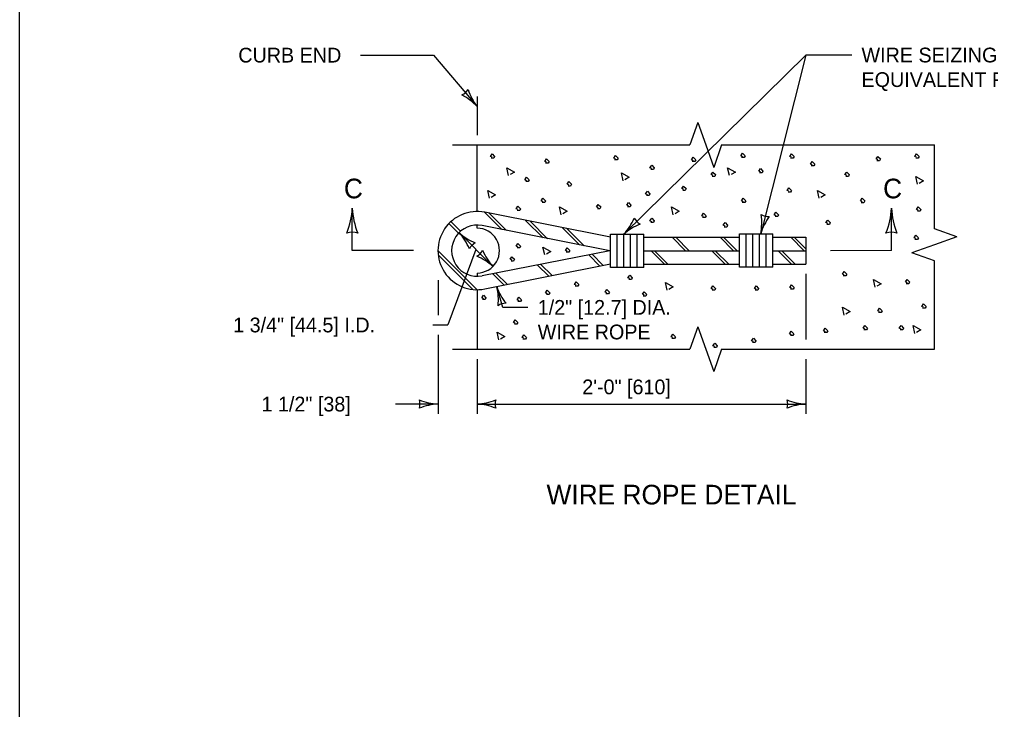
# Model space of a CAD drawing. Extents: x 49991.4 to 50021, y 49987.6 to 50011.4.
# Drawn here: x 49999.384 to 50003.334, y 49991.042 to 49993.85 of the extents above; entities that cross this region are included whole.
import ezdxf

# ---------------------------------------------------------------- set-up
doc = ezdxf.new("R2010")
doc.units = 0
for name, color, linetype in [('Level 1', 7, 'Continuous'), ('Level 2', 7, 'Continuous'), ('Level 3', 7, 'Continuous'), ('Level 6', 7, 'Continuous')]:
    doc.layers.add(name, color=color, linetype=linetype)

msp = doc.modelspace()

# ---------------------------------------------------------------- linework, layer by layer
at = {"layer": 'Level 1'}
for p, q in [((50001.245, 49993.0684), (50001.245, 49993.3392)), ((50001.2758, 49993.0654), (50001.3461, 49992.9952)), ((50001.7873, 49992.9636), (50001.276, 49993.0653)), ((50001.2937, 49993.0618), (50001.3647, 49992.9912)), ((50001.1303, 49993.0196), (50001.1694, 49992.9806)), ((50001.1385, 49993.0275), (50001.178, 49992.9885)), ((50001.245, 49993.0009), (50001.245, 49993.013)), ((50001.7854, 49992.9084), (50001.2652, 49993.011)), ((50001.4426, 49993.0322), (50001.5134, 49992.9615)), ((50001.4607, 49993.0286), (50001.5314, 49992.9575)), ((50001.5924, 49993.0024), (50001.6621, 49992.9324)), ((50001.61, 49992.9989), (50001.6806, 49992.9283)), ((50001.7873, 49992.976), (50001.923, 49992.976)), ((50001.7873, 49992.8403), (50001.7873, 49992.976)), ((50001.7873, 49992.9636), (50001.7873, 49992.9636)), ((50001.8145, 49992.8403), (50001.8145, 49992.976)), ((50001.8415, 49992.8403), (50001.8415, 49992.976)), ((50001.8688, 49992.8403), (50001.8688, 49992.976)), ((50001.8958, 49992.8403), (50001.8958, 49992.976)), ((50001.923, 49992.8403), (50001.923, 49992.976)), ((50001.923, 49992.9636), (50002.3128, 49992.9636)), ((50002.0391, 49992.9636), (50002.0932, 49992.9091)), ((50002.0531, 49992.9636), (50002.1072, 49992.9091)), ((50002.2337, 49992.9641), (50002.2884, 49992.9091)), ((50002.248, 49992.9641), (50002.3025, 49992.9091)), ((50002.3128, 49992.978), (50002.4483, 49992.978)), ((50002.3128, 49992.8424), (50002.3128, 49992.978)), ((50002.3399, 49992.8424), (50002.3399, 49992.978)), ((50002.3668, 49992.8424), (50002.3668, 49992.978)), ((50002.3943, 49992.8424), (50002.3943, 49992.978)), ((50002.4209, 49992.8424), (50002.4209, 49992.978)), ((50002.4483, 49992.8424), (50002.4483, 49992.978)), ((50002.4483, 49992.9636), (50002.582, 49992.9636)), ((50002.5214, 49992.9636), (50002.5761, 49992.9091)), ((50002.5351, 49992.9636), (50002.582, 49992.9169)), ((50002.582, 49992.9636), (50002.582, 49992.8548)), ((50001.086, 49992.9096), (50001.245, 49992.7503)), ((50001.0869, 49992.8922), (50001.2276, 49992.7513)), ((50001.7854, 49992.9084), (50001.2651, 49992.8073)), ((50001.6998, 49992.8918), (50001.7449, 49992.8465)), ((50001.7134, 49992.8945), (50001.7584, 49992.8492)), ((50001.923, 49992.9091), (50002.3128, 49992.9091)), ((50001.9532, 49992.9091), (50002.0075, 49992.8549)), ((50001.9672, 49992.9091), (50002.0211, 49992.8549)), ((50002.2001, 49992.9091), (50002.2546, 49992.8549)), ((50002.214, 49992.9091), (50002.2686, 49992.8549)), ((50002.4483, 49992.9091), (50002.582, 49992.9091)), ((50002.4699, 49992.9091), (50002.5242, 49992.8548)), ((50002.484, 49992.9091), (50002.5382, 49992.8548)), ((50001.7873, 49992.8549), (50001.2761, 49992.7531)), ((50001.4912, 49992.8502), (50001.5363, 49992.805)), ((50001.5034, 49992.8539), (50001.5498, 49992.8077)), ((50001.7873, 49992.8549), (50001.7873, 49992.8549)), ((50001.923, 49992.8549), (50002.3128, 49992.8549)), ((50002.4483, 49992.8548), (50002.582, 49992.8548)), ((50001.245, 49992.8178), (50001.245, 49992.8054)), ((50001.3081, 49992.8157), (50001.355, 49992.7689)), ((50001.3215, 49992.8183), (50001.3682, 49992.7715)), ((50001.923, 49992.8403), (50001.7873, 49992.8403)), ((50002.4483, 49992.8424), (50002.3128, 49992.8424)), ((50001.245, 49992.7503), (50001.245, 49992.5083))]:
    msp.add_line(p, q, dxfattribs=at)
msp.add_lwpolyline([(49999.3835, 49998.9992), (50016.7501, 49998.9992), (50016.7501, 49987.7988), (49999.3835, 49987.7988)], close=True, dxfattribs=at)
for points in [[(50001.306, 49993.2894), (50001.299, 49993.293), (50001.306, 49993.3036), (50001.3165, 49993.293), (50001.313, 49993.2859), (50001.3025, 49993.2859)], [(50001.5271, 49993.2681), (50001.5201, 49993.2717), (50001.5271, 49993.2823), (50001.5376, 49993.2717), (50001.5341, 49993.2646), (50001.5236, 49993.2646)], [(50001.8079, 49993.2823), (50001.8009, 49993.2859), (50001.8079, 49993.2965), (50001.8184, 49993.2859), (50001.8149, 49993.2788), (50001.8044, 49993.2788)], [(50002.1237, 49993.2752), (50002.1167, 49993.2788), (50002.1237, 49993.2894), (50002.1342, 49993.2788), (50002.1307, 49993.2717), (50002.1202, 49993.2717)], [(50002.3246, 49993.2913), (50002.3176, 49993.2949), (50002.3246, 49993.3055), (50002.3351, 49993.2949), (50002.3316, 49993.2878), (50002.3211, 49993.2878)], [(50002.5238, 49993.2894), (50002.5168, 49993.293), (50002.5238, 49993.3036), (50002.5343, 49993.293), (50002.5308, 49993.2859), (50002.5203, 49993.2859)], [(50002.8748, 49993.2788), (50002.8678, 49993.2824), (50002.8748, 49993.293), (50002.8853, 49993.2824), (50002.8818, 49993.2753), (50002.8713, 49993.2753)], [(50003.0327, 49993.2894), (50003.0257, 49993.293), (50003.0327, 49993.3036), (50003.0432, 49993.293), (50003.0397, 49993.2859), (50003.0292, 49993.2859)], [(50001.3728, 49993.2149), (50001.3657, 49993.2469), (50001.3973, 49993.2291), (50001.3798, 49993.2185)], [(50001.9553, 49993.2433), (50001.9483, 49993.2469), (50001.9553, 49993.2575), (50001.9658, 49993.2469), (50001.9623, 49993.2398), (50001.9518, 49993.2398)], [(50002.2712, 49993.2149), (50002.2641, 49993.2469), (50002.2957, 49993.2291), (50002.2782, 49993.2185)], [(50002.3975, 49993.2291), (50002.3905, 49993.2327), (50002.3975, 49993.2433), (50002.408, 49993.2327), (50002.4045, 49993.2256), (50002.394, 49993.2256)], [(50002.6081, 49993.2575), (50002.6011, 49993.2611), (50002.6081, 49993.2717), (50002.6186, 49993.2611), (50002.6151, 49993.254), (50002.6046, 49993.254)], [(50001.4464, 49993.1936), (50001.4394, 49993.1972), (50001.4464, 49993.2078), (50001.4569, 49993.1972), (50001.4534, 49993.1901), (50001.4429, 49993.1901)], [(50001.8395, 49993.1936), (50001.8324, 49993.2256), (50001.864, 49993.2078), (50001.8465, 49993.1972)], [(50002.2045, 49993.2149), (50002.1975, 49993.2185), (50002.2045, 49993.2291), (50002.215, 49993.2185), (50002.2115, 49993.2114), (50002.201, 49993.2114)], [(50002.7484, 49993.2149), (50002.7414, 49993.2185), (50002.7484, 49993.2291), (50002.7589, 49993.2185), (50002.7554, 49993.2114), (50002.7449, 49993.2114)], [(50003.0363, 49993.1794), (50003.0292, 49993.2114), (50003.0608, 49993.1936), (50003.0433, 49993.183)], [(50001.6184, 49993.1758), (50001.6114, 49993.1794), (50001.6184, 49993.19), (50001.6289, 49993.1794), (50001.6254, 49993.1723), (50001.6149, 49993.1723)], [(50002.0851, 49993.1581), (50002.0781, 49993.1617), (50002.0851, 49993.1723), (50002.0956, 49993.1617), (50002.0921, 49993.1546), (50002.0816, 49993.1546)], [(50002.5133, 49993.151), (50002.5063, 49993.1546), (50002.5133, 49993.1652), (50002.5238, 49993.1546), (50002.5203, 49993.1475), (50002.5098, 49993.1475)], [(50001.2955, 49993.1226), (50001.2884, 49993.1546), (50001.32, 49993.1368), (50001.3025, 49993.1262)], [(50001.5131, 49993.1084), (50001.5061, 49993.112), (50001.5131, 49993.1226), (50001.5236, 49993.112), (50001.5201, 49993.1049), (50001.5096, 49993.1049)], [(50001.9377, 49993.1368), (50001.9307, 49993.1404), (50001.9377, 49993.151), (50001.9482, 49993.1404), (50001.9447, 49993.1333), (50001.9342, 49993.1333)], [(50002.3273, 49993.1084), (50002.3203, 49993.112), (50002.3273, 49993.1226), (50002.3378, 49993.112), (50002.3343, 49993.1049), (50002.3238, 49993.1049)], [(50002.6362, 49993.1226), (50002.6291, 49993.1546), (50002.6607, 49993.1368), (50002.6432, 49993.1262)], [(50002.8115, 49993.108), (50002.8045, 49993.1116), (50002.8115, 49993.1222), (50002.822, 49993.1116), (50002.8185, 49993.1045), (50002.808, 49993.1045)], [(50001.4113, 49993.0764), (50001.4043, 49993.08), (50001.4113, 49993.0906), (50001.4218, 49993.08), (50001.4183, 49993.0729), (50001.4078, 49993.0729)], [(50001.5868, 49993.0551), (50001.5797, 49993.0871), (50001.6113, 49993.0693), (50001.5938, 49993.0587)], [(50001.7377, 49993.0835), (50001.7307, 49993.0871), (50001.7377, 49993.0977), (50001.7482, 49993.0871), (50001.7447, 49993.08), (50001.7342, 49993.08)], [(50001.8605, 49993.0906), (50001.8535, 49993.0942), (50001.8605, 49993.1048), (50001.871, 49993.0942), (50001.8675, 49993.0871), (50001.857, 49993.0871)], [(50002.0431, 49993.0551), (50002.036, 49993.0871), (50002.0676, 49993.0693), (50002.0501, 49993.0587)], [(50003.0397, 49993.0729), (50003.0327, 49993.0765), (50003.0397, 49993.0871), (50003.0502, 49993.0765), (50003.0467, 49993.0694), (50003.0362, 49993.0694)], [(50001.9553, 49993.0267), (50001.9483, 49993.0303), (50001.9553, 49993.0409), (50001.9658, 49993.0303), (50001.9623, 49993.0232), (50001.9518, 49993.0232)], [(50002.1659, 49993.048), (50002.1589, 49993.0516), (50002.1659, 49993.0622), (50002.1764, 49993.0516), (50002.1729, 49993.0445), (50002.1624, 49993.0445)], [(50002.4607, 49993.0516), (50002.4537, 49993.0552), (50002.4607, 49993.0658), (50002.4712, 49993.0552), (50002.4677, 49993.0481), (50002.4572, 49993.0481)], [(50002.2536, 49993.009), (50002.2466, 49993.0126), (50002.2536, 49993.0232), (50002.2641, 49993.0126), (50002.2606, 49993.0055), (50002.2501, 49993.0055)], [(50002.6712, 49993.0196), (50002.6642, 49993.0232), (50002.6712, 49993.0338), (50002.6817, 49993.0232), (50002.6782, 49993.0161), (50002.6677, 49993.0161)], [(50003.0296, 49992.9585), (50003.0226, 49992.9621), (50003.0296, 49992.9727), (50003.0401, 49992.9621), (50003.0366, 49992.955), (50003.0261, 49992.955)], [(50001.4113, 49992.9238), (50001.4043, 49992.9274), (50001.4113, 49992.938), (50001.4218, 49992.9274), (50001.4183, 49992.9203), (50001.4078, 49992.9203)], [(50001.5202, 49992.8918), (50001.5131, 49992.9238), (50001.5447, 49992.906), (50001.5272, 49992.8954)], [(50001.3867, 49992.8705), (50001.3797, 49992.8741), (50001.3867, 49992.8847), (50001.3972, 49992.8741), (50001.3937, 49992.867), (50001.3832, 49992.867)], [(50001.6114, 49992.906), (50001.6044, 49992.9096), (50001.6114, 49992.9202), (50001.6219, 49992.9096), (50001.6184, 49992.9025), (50001.6079, 49992.9025)], [(50001.8657, 49992.7953), (50001.8587, 49992.7989), (50001.8657, 49992.8095), (50001.8762, 49992.7989), (50001.8727, 49992.7918), (50001.8622, 49992.7918)], [(50002.7379, 49992.8102), (50002.7309, 49992.8138), (50002.7379, 49992.8244), (50002.7484, 49992.8138), (50002.7449, 49992.8067), (50002.7344, 49992.8067)], [(50001.6481, 49992.7684), (50001.6411, 49992.772), (50001.6481, 49992.7826), (50001.6586, 49992.772), (50001.6551, 49992.7649), (50001.6446, 49992.7649)], [(50002.0185, 49992.7481), (50002.0114, 49992.7801), (50002.043, 49992.7623), (50002.0255, 49992.7517)], [(50002.2045, 49992.7516), (50002.1975, 49992.7552), (50002.2045, 49992.7658), (50002.215, 49992.7552), (50002.2115, 49992.7481), (50002.201, 49992.7481)], [(50002.3799, 49992.7516), (50002.3729, 49992.7552), (50002.3799, 49992.7658), (50002.3904, 49992.7552), (50002.3869, 49992.7481), (50002.3764, 49992.7481)], [(50002.5239, 49992.7554), (50002.5169, 49992.759), (50002.5239, 49992.7696), (50002.5344, 49992.759), (50002.5309, 49992.7519), (50002.5204, 49992.7519)], [(50002.8643, 49992.7605), (50002.8572, 49992.7925), (50002.8888, 49992.7747), (50002.8713, 49992.7641)], [(50002.9941, 49992.7782), (50002.9871, 49992.7818), (50002.9941, 49992.7924), (50003.0046, 49992.7818), (50003.0011, 49992.7747), (50002.9906, 49992.7747)], [(50001.2707, 49992.7137), (50001.2637, 49992.7173), (50001.2707, 49992.7279), (50001.2812, 49992.7173), (50001.2777, 49992.7102), (50001.2672, 49992.7102)], [(50001.5306, 49992.7339), (50001.5236, 49992.7375), (50001.5306, 49992.7481), (50001.5411, 49992.7375), (50001.5376, 49992.7304), (50001.5271, 49992.7304)], [(50001.7728, 49992.7374), (50001.7658, 49992.741), (50001.7728, 49992.7516), (50001.7833, 49992.741), (50001.7798, 49992.7339), (50001.7693, 49992.7339)], [(50001.9243, 49992.728), (50001.9173, 49992.7316), (50001.9243, 49992.7422), (50001.9348, 49992.7316), (50001.9313, 49992.7245), (50001.9208, 49992.7245)], [(50001.4148, 49992.7055), (50001.4078, 49992.7091), (50001.4148, 49992.7197), (50001.4253, 49992.7091), (50001.4218, 49992.702), (50001.4113, 49992.702)], [(50003.0608, 49992.6788), (50003.0538, 49992.6824), (50003.0608, 49992.693), (50003.0713, 49992.6824), (50003.0678, 49992.6753), (50003.0573, 49992.6753)], [(50002.738, 49992.6469), (50002.7309, 49992.6789), (50002.7625, 49992.6611), (50002.745, 49992.6505)], [(50002.8818, 49992.6611), (50002.8748, 49992.6647), (50002.8818, 49992.6753), (50002.8923, 49992.6647), (50002.8888, 49992.6576), (50002.8783, 49992.6576)], [(50001.4001, 49992.6132), (50001.3931, 49992.6168), (50001.4001, 49992.6274), (50001.4106, 49992.6168), (50001.4071, 49992.6097), (50001.3966, 49992.6097)], [(50001.3333, 49992.546), (50001.3262, 49992.578), (50001.3578, 49992.5602), (50001.3403, 49992.5496)], [(50001.4349, 49992.5528), (50001.4279, 49992.5564), (50001.4349, 49992.567), (50001.4454, 49992.5564), (50001.4419, 49992.5493), (50001.4314, 49992.5493)], [(50002.041, 49992.5555), (50002.034, 49992.5591), (50002.041, 49992.5697), (50002.0515, 49992.5591), (50002.048, 49992.552), (50002.0375, 49992.552)], [(50002.5228, 49992.5669), (50002.5158, 49992.5705), (50002.5228, 49992.5811), (50002.5333, 49992.5705), (50002.5298, 49992.5634), (50002.5193, 49992.5634)], [(50002.6607, 49992.5794), (50002.6537, 49992.583), (50002.6607, 49992.5936), (50002.6712, 49992.583), (50002.6677, 49992.5759), (50002.6572, 49992.5759)], [(50002.8221, 49992.59), (50002.8151, 49992.5936), (50002.8221, 49992.6042), (50002.8326, 49992.5936), (50002.8291, 49992.5865), (50002.8186, 49992.5865)], [(50002.9695, 49992.59), (50002.9625, 49992.5936), (50002.9695, 49992.6042), (50002.98, 49992.5936), (50002.9765, 49992.5865), (50002.966, 49992.5865)], [(50003.0258, 49992.5723), (50003.0187, 49992.6043), (50003.0503, 49992.5865), (50003.0328, 49992.5759)], [(50002.2115, 49992.5189), (50002.2045, 49992.5225), (50002.2115, 49992.5331), (50002.222, 49992.5225), (50002.2185, 49992.5154), (50002.208, 49992.5154)], [(50002.3688, 49992.5393), (50002.3618, 49992.5429), (50002.3688, 49992.5535), (50002.3793, 49992.5429), (50002.3758, 49992.5358), (50002.3653, 49992.5358)]]:
    msp.add_lwpolyline(points, dxfattribs=at)
for centre, radius, start, end in [((50001.245, 49992.9094), 0.159, 78.7514, 281.2486), ((50001.2452, 49992.9092), 0.1038, 78.8937, 281.05), ((50001.245, 49992.9094), 0.0912, 269.8974, 90.1017)]:
    msp.add_arc(centre, radius, start, end, dxfattribs=at)
at = {"layer": 'Level 3'}
for p, q in [((50000.7706, 49993.7049), (50001.0675, 49993.7049)), ((50001.0672, 49993.7053), (50001.245, 49993.4961)), ((50002.5818, 49993.7053), (50001.842, 49992.976)), ((50002.5818, 49993.7053), (50002.3987, 49992.978)), ((50002.7687, 49993.7053), (50002.5818, 49993.7053)), ((50001.245, 49993.5361), (50001.245, 49993.3792)), ((50001.3095, 49992.8449), (50001.1717, 49992.9827)), ((50001.2406, 49992.9138), (50001.1262, 49992.6068)), ((50002.582, 49992.8148), (50002.582, 49992.5483)), ((50001.0862, 49992.7892), (50001.0862, 49992.6468)), ((50001.3503, 49992.6783), (50001.3249, 49992.7629)), ((50001.4518, 49992.6783), (50001.3503, 49992.6783)), ((50001.0647, 49992.6068), (50001.1262, 49992.6068)), ((50001.0862, 49992.5668), (50001.0862, 49992.2449)), ((50001.245, 49992.4683), (50001.245, 49992.2449)), ((50002.582, 49992.4683), (50002.582, 49992.2449)), ((50001.0862, 49992.2849), (50000.9127, 49992.2849)), ((50001.245, 49992.2849), (50002.582, 49992.2849))]:
    msp.add_line(p, q, dxfattribs=at)
for centre, radius, start, end in [((50001.162, 49993.5938), 0.0548, 292.4945, 328.2168), ((50001.4202, 49993.6329), 0.2223, 197.8117, 217.9952), ((50001.0751, 49993.3366), 0.233, 43.183, 62.4328), ((50000.4413, 49993.0945), 0.2964, 337.456, 357.6395), ((50001.0477, 49993.0976), 0.3107, 182.8273, 202.0772), ((50002.6343, 49993.0944), 0.2964, 337.456, 357.6395), ((50003.2408, 49993.0975), 0.3107, 182.8273, 202.0772), ((50001.6704, 49993.1337), 0.233, 317.4153, 336.6652), ((50001.9333, 49993.0661), 0.0548, 206.7268, 242.4492), ((50002.1702, 49993.0237), 0.233, 348.6916, 7.9415), ((50002.6118, 49992.9149), 0.2223, 143.3203, 163.5038), ((50002.43, 49993.1024), 0.0548, 238.0031, 273.7255), ((50001.9914, 49992.8114), 0.2223, 112.044, 132.2275), ((50000.7375, 49992.9113), 0.073, 72.1388, 107.8612), ((50001.0082, 49992.8321), 0.2223, 22.456, 42.6395), ((50001.3282, 49993.1554), 0.233, 227.8273, 247.0772), ((50002.9305, 49992.9112), 0.073, 72.1388, 107.8612), ((50001.2624, 49992.892), 0.0548, 117.1388, 152.8612), ((50001.2189, 49992.9356), 0.0548, 297.1388, 332.8612), ((50001.1531, 49992.6722), 0.233, 47.8273, 67.0772), ((50001.4731, 49992.9955), 0.2223, 202.456, 222.6395), ((50001.1095, 49992.7076), 0.2223, 354.2141, 14.3976), ((50001.5444, 49992.841), 0.233, 199.5854, 218.8352), ((50001.3618, 49992.6401), 0.0548, 88.8969, 124.6192), ((50001.0953, 49992.5071), 0.2223, 247.456, 267.6395), ((50000.958, 49992.2849), 0.0548, 342.1388, 17.8612), ((50001.2335, 49992.5177), 0.233, 272.8273, 292.0772), ((50001.3732, 49992.2849), 0.0548, 162.1388, 197.8612), ((50002.5911, 49992.5071), 0.2223, 247.456, 267.6395), ((50002.4538, 49992.2849), 0.0548, 342.1388, 17.8612), ((50001.0977, 49992.0522), 0.233, 92.8273, 112.0772), ((50001.2358, 49992.0628), 0.2223, 67.456, 87.6395), ((50002.5935, 49992.0522), 0.233, 92.8273, 112.0772)]:
    msp.add_arc(centre, radius, start, end, dxfattribs=at)
at = {"layer": 'Level 6'}
for p, q in [((50002.1426, 49993.4306), (50002.1102, 49993.3392)), ((50002.1426, 49993.4306), (50002.175, 49993.3392)), ((50001.145, 49993.3392), (50002.1102, 49993.3392)), ((50002.175, 49993.3392), (50002.2074, 49993.2478)), ((50002.2398, 49993.3392), (50002.2074, 49993.2478)), ((50002.2398, 49993.3392), (50003.105, 49993.3392)), ((50003.105, 49992.9975), (50003.105, 49993.3392)), ((50000.7375, 49992.9093), (50000.7375, 49993.0822)), ((50002.9305, 49992.9093), (50002.9305, 49993.0821)), ((50003.1964, 49992.9651), (50003.105, 49992.9975)), ((50003.1964, 49992.9651), (50003.105, 49992.9327)), ((50003.105, 49992.9327), (50003.0136, 49992.9003)), ((50000.986, 49992.9093), (50000.7375, 49992.9093)), ((50002.9305, 49992.9093), (50002.682, 49992.9092)), ((50003.105, 49992.8679), (50003.0136, 49992.9003)), ((50003.105, 49992.5083), (50003.105, 49992.8679)), ((50002.1426, 49992.5997), (50002.1102, 49992.5083)), ((50002.1426, 49992.5997), (50002.175, 49992.5083)), ((50001.145, 49992.5083), (50002.1102, 49992.5083)), ((50002.175, 49992.5083), (50002.2074, 49992.4169)), ((50002.2398, 49992.5083), (50002.2074, 49992.4169)), ((50002.2398, 49992.5083), (50003.105, 49992.5083))]:
    msp.add_line(p, q, dxfattribs=at)

# ---------------------------------------------------------------- texts
at = {"layer": 'Level 2'}
for s, height, p in [('CURB END', 0.06, (50000.2738, 49993.6749)), ('WIRE SEIZING OR', 0.06, (50002.8087, 49993.6753)), ('EQUIVALENT FASTENING', 0.06, (50002.8087, 49993.5753)), ('C', 0.08, (50000.7034, 49993.1222)), ('C', 0.08, (50002.8965, 49993.1221)), ('1/2" [12.7] DIA.', 0.06, (50001.4918, 49992.6483)), ('1 3/4" [44.5] I.D.', 0.06, (50000.253, 49992.5768)), ('WIRE ROPE', 0.06, (50001.4918, 49992.5483)), ('2\'-0" [610]', 0.06, (50001.6729, 49992.3249)), ('1 1/2" [38]', 0.06, (50000.3682, 49992.2549)), ('WIRE ROPE DETAIL', 0.08, (50001.5276, 49991.8765))]:
    msp.add_text(s, height=height, dxfattribs=at).set_placement(p)

doc.saveas('drawing.dxf')
